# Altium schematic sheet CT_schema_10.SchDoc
size 147 x 119 mm
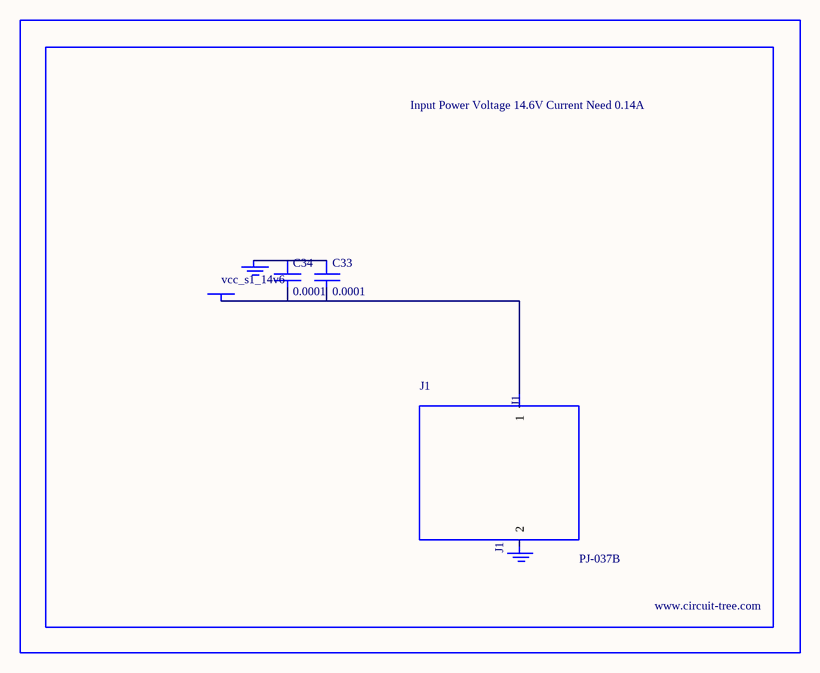
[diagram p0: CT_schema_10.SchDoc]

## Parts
BORDER9  (no value)
C33  0.0001  [EXV-9H]
C34  0.0001  [EXV-9H]
GND_INSTANCE_9_0  (no value)
GND_INSTANCE_9_1  (no value)
J1  PJ-037B  [PJ-037B_PACKAGE]
POWER_INSTANCE_9_0  vcc_s1_14v6

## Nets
NetC33_1: C33.1 C34.1 GND_INSTANCE_9_0.0(GND)
NetC33_2: C33.2 C34.2 J1.1 POWER_INSTANCE_9_0.0(PWR)

Not connected (* = marked no-connect by the designer): GND_INSTANCE_9_1 0(GND); J1 2

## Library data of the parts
BORDER9 = BORDER_PAGE9
C33 C34 = EDK107M035A9HAA
GND_INSTANCE_9_0 GND_INSTANCE_9_1 = GND
POWER_INSTANCE_9_0 = PWR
